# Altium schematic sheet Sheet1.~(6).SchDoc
size A3
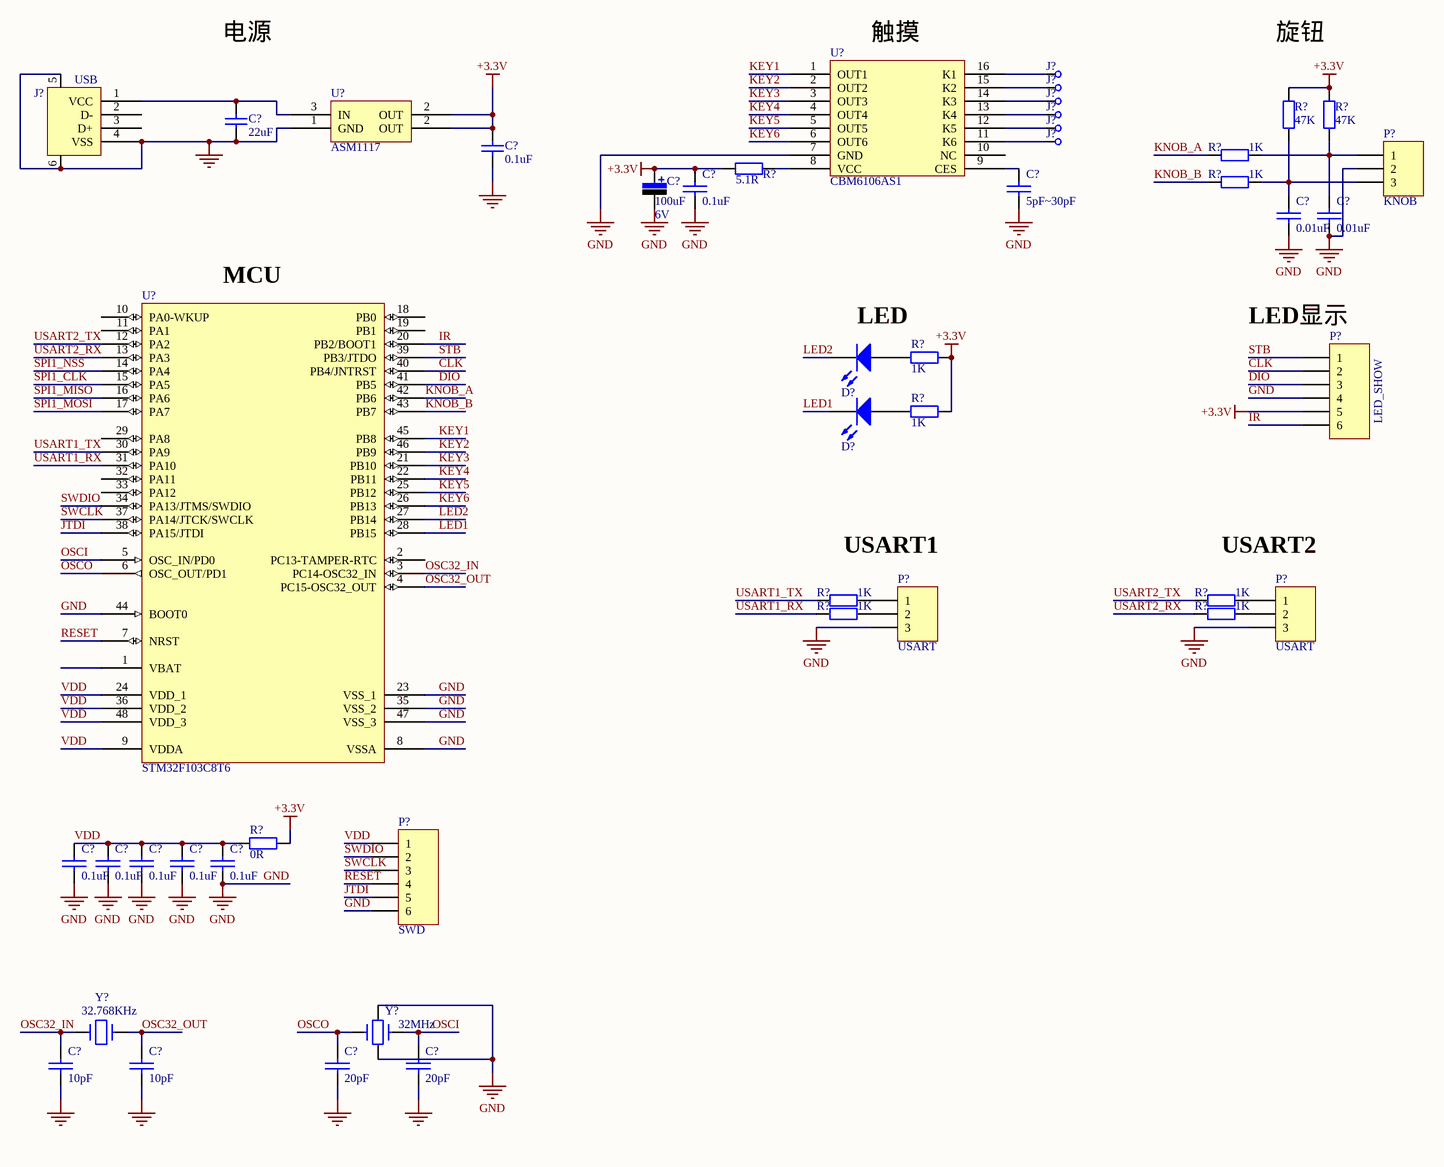
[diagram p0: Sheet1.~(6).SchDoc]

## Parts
(Parts that share a designator on the sheet are numbered #1, #2 ... from top to bottom, then left to right.)
C?#1  value 22uF  [0402C]  (hidden comment: Cap)
C?#2  value 0.1uF  [0402C]  (hidden comment: Cap)
C?#3  value 100uF  Vol: 6V  [CAP-3528]  (hidden comment: Cap Pol)
C?#4  0.1uF  [0402C]
C?#5  5pF~30pF  [0402C]
C?#6  0.01uF  [0402C]
C?#7  0.01uF  [0402C]
C?#8  0.1uF  [0402C]
C?#9  0.1uF  [0402C]
C?#10  0.1uF  [0402C]
C?#11  0.1uF  [0402C]
C?#12  0.1uF  [0402C]
C?#13  10pF  [0402C]
C?#14  10pF  [0402C]
C?#15  20pF  [0402C]
C?#16  20pF  [0402C]
D?#1  LED0  [led0603]  (value not drawn)
D?#2  LED0  [led0603]  (value not drawn)
J?#1  CHECK  [CHECK-A]  (value not drawn)
J?#2  USB  [USB_A1]
J?#3  CHECK  [CHECK-A]  (value not drawn)
J?#4  CHECK  [CHECK-A]  (value not drawn)
J?#5  CHECK  [CHECK-A]  (value not drawn)
J?#6  CHECK  [CHECK-A]  (value not drawn)
J?#7  CHECK  [CHECK-A]  (value not drawn)
P?#1  KNOB  [HDR3X1_A]
P?#2  LED_SHOW  [HDR6X1_B2]
P?#3  USART  [HDR3X1_A]
P?#4  USART  [HDR3X1_A]
P?#5  SWD  [HDR6X1_B2]
R?#1  value 47K  [0603-1]  (hidden comment: Res1)
R?#2  value 47K  [0603-1]  (hidden comment: Res1)
R?#3  value 1K  [0603-1]  (hidden comment: Res1)
R?#4  value 5.1R  [0603-1]  (hidden comment: Res1)
R?#5  value 1K  [0603-1]  (hidden comment: Res1)
R?#6  value 1K  [0402R]  (hidden comment: Res1)
R?#7  value 1K  [0402R]  (hidden comment: Res1)
R?#8  value 1K  [0402R]  (hidden comment: Res1)
R?#9  value 1K  [0402R]  (hidden comment: Res1)
R?#10  value 1K  [0402R]  (hidden comment: Res1)
R?#11  value 1K  [0402R]  (hidden comment: Res1)
R?#12  value 0R  [0402R]  (hidden comment: Res1)
U?#1  ASM1117  [SOT-223-3]
U?#2  CBM6106AS1
U?#3  STM32F103C8T6  [LQFP48_N]
Y?#1  32.768KHz  [SMD3215]
Y?#2  32MHz  [Y3225]

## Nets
+3.3V: C?#2.2 C?#3.1 C?#4.1 P?#2.5 R?#1.2 R?#2.2 R?#4.1 R?#6.1 R?#7.1 R?#12.2 U?#1.2(OUT)
GND: C?#1.1 C?#2.1 C?#3.2 C?#4.2 C?#5.2 C?#6.2 C?#7.2 C?#8.2 C?#9.2 C?#10.2 C?#11.2 C?#12.2 C?#13.2 C?#14.2 C?#15.2 C?#16.2 J?#2.4(VSS) J?#2.5 J?#2.6 P?#1.2 P?#2.4 P?#3.3 P?#4.3 P?#5.6 U?#1.1(GND) U?#2.7(GND) U?#3.8(VSSA) U?#3.23(VSS_1) U?#3.35(VSS_2) U?#3.44(BOOT0) U?#3.47(VSS_3) Y?#2.2 Y?#2.4
CLK: P?#2.2 U?#3.40(PB4/JNTRST)
DIO: P?#2.3 U?#3.41(PB5)
IR: P?#2.6 U?#3.20(PB2/BOOT1)
JTDI: P?#5.5 U?#3.38(PA15/JTDI)
KEY1: U?#2.1(OUT1) U?#3.45(PB8)
KEY2: U?#2.2(OUT2) U?#3.46(PB9)
KEY3: U?#2.3(OUT3) U?#3.21(PB10)
KEY4: U?#2.4(OUT4) U?#3.22(PB11)
KEY5: U?#2.5(OUT5) U?#3.25(PB12)
KEY6: U?#2.6(OUT6) U?#3.26(PB13)
KNOB_A: R?#3.1 U?#3.42(PB6)
KNOB_B: R?#5.1 U?#3.43(PB7)
LED1: D?#2.2(K) U?#3.28(PB15)
LED2: D?#1.2(K) U?#3.27(PB14)
OSC32_IN: C?#13.1 U?#3.3(PC14-OSC32_IN) Y?#1.1
OSC32_OUT: C?#14.1 U?#3.4(PC15-OSC32_OUT) Y?#1.2
OSCI: C?#16.1 U?#3.5(OSC_IN/PD0) Y?#2.3
OSCO: C?#15.1 U?#3.6(OSC_OUT/PD1) Y?#2.1
RESET: P?#5.4 U?#3.7(NRST)
SPI1_CLK: U?#3.15(PA5)
SPI1_MISO: U?#3.16(PA6)
SPI1_MOSI: U?#3.17(PA7)
SPI1_NSS: U?#3.14(PA4)
STB: P?#2.1 U?#3.39(PB3/JTDO)
SWCLK: P?#5.3 U?#3.37(PA14/JTCK/SWCLK)
SWDIO: P?#5.2 U?#3.34(PA13/JTMS/SWDIO)
USART1_RX: R?#10.2 U?#3.31(PA10)
USART1_TX: R?#8.2 U?#3.30(PA9)
USART2_RX: R?#11.2 U?#3.13(PA3)
USART2_TX: R?#9.2 U?#3.12(PA2)
VDD: C?#8.1 C?#9.1 C?#10.1 C?#11.1 C?#12.1 P?#5.1 R?#12.1 U?#3.9(VDDA) U?#3.24(VDD_1) U?#3.36(VDD_2) U?#3.48(VDD_3)
NetC?#1_2: C?#1.2 J?#2.1(VCC) U?#1.3(IN)
NetC?#5_1: C?#5.1 U?#2.9(CES)
NetC?#6_1: C?#6.1 P?#1.3 R?#1.1 R?#5.2
NetC?#7_1: C?#7.1 P?#1.1 R?#2.1 R?#3.2
NetD?#1_1: D?#1.1(A) R?#6.2
NetD?#2_1: D?#2.1(A) R?#7.2
NetJ?#1_1: J?#1.1 U?#2.16(K1)
NetJ?#3_1: J?#3.1 U?#2.15(K2)
NetJ?#4_1: J?#4.1 U?#2.14(K3)
NetJ?#5_1: J?#5.1 U?#2.13(K4)
NetJ?#6_1: J?#6.1 U?#2.12(K5)
NetJ?#7_1: J?#7.1 U?#2.11(K6)
NetP?#3_1: P?#3.1 R?#8.1
NetP?#3_2: P?#3.2 R?#10.1
NetP?#4_1: P?#4.1 R?#9.1
NetP?#4_2: P?#4.2 R?#11.1
NetR?#4_2: R?#4.2 U?#2.8(VCC)

Not connected (* = marked no-connect by the designer): J?#2 2(D-) 3(D+); U?#2 10(NC); U?#3 1(VBAT) 2(PC13-TAMPER-RTC) 10(PA0-WKUP) 11(PA1) 18(PB0) 19(PB1) 29(PA8) 32(PA11) 33(PA12)

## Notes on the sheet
- 电源
- (near U?#2) 触摸
- 旋钮
- (near U?#3) MCU
- LED
- (near P?#2) LED显示
- USART1
- USART2

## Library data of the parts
C?#1 C?#2 = Cap: 无极性电容
C?#3 = Cap Pol: 极性电解电容
C?#4-C?#16 = CAP: Capacitor
D?#1 D?#2 = LED0: 发光二极管
J?#1 J?#3-J?#7 = CHECK: 测试点
J?#2 = USB: USB接口
P?#1 P?#3 P?#4 = Header 3: 接插件
P?#2 P?#5 = Header 6: 接插件
R?#1-R?#12 = Res1: 贴片电阻
U?#1 = ASM1117: 3.3V稳压芯片
U?#3 = STM32F103C8T6: STM32 ARM-based 32-bit MCU with 64 Kbytes Flash, 48-pin LQFP, Industrial Temperature
Y?#1 = CRYSTAL
Y?#2 = CRYSTAL1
